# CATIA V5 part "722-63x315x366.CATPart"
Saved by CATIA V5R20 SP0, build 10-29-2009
Part number: 722-63x315x366
Definition: NONE
Nomenclature: 722-63x315x366
Source: Unknown
Description: 722-63x315x366
Bounding box of the stored display mesh (mm): x -31.5 to 31.5, y -31.5 to 31.5, z -297 to 69
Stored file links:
  C:\Users\Utente\Desktop\IO LAVORO\3D X SITO CF\X SITO\722\722-63x315x366.CATPart
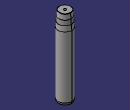
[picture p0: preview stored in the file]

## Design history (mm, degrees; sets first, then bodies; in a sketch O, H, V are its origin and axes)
Body1 "722-63x315x366" (main body)
  Solid1: solid without history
